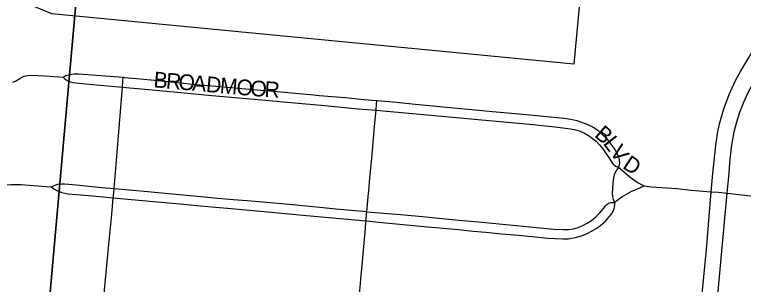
# Model space of a CAD drawing. Extents: x -209 to 4852, y 0 to 905.
# Drawn here: x 111.72 to 120.48, y 309.86 to 313.11 of the extents above; entities that cross this region are included whole.
import ezdxf

# ---------------------------------------------------------------- set-up
doc = ezdxf.new("R2010")
doc.units = 0
for name, color, linetype in [('GM_X_Airport_Location_Class_2', 7, 'Continuous'), ('GM_X_Airport_Location_Class_3', 7, 'Continuous'), ('GM_X_Minor_River', 7, 'Continuous'), ('GM_X_US_Location', 7, 'Continuous')]:
    doc.layers.add(name, color=color, linetype=linetype)

msp = doc.modelspace()

# ---------------------------------------------------------------- linework, layer by layer
at = {"layer": 'GM_X_Airport_Location_Class_2'}
for points in [[(120.0972, 310.975), (120.1155, 311.1929), (120.1467, 311.4975), (120.1715, 311.6747), (120.1963, 311.7933), (120.2473, 311.9704), (120.3118, 312.1446), (120.3881, 312.3128), (120.4482, 312.4205), (120.5455, 312.5798), (120.5778, 312.636), (120.6413, 312.7425), (120.7043, 312.8515), (120.7301, 312.9054), (120.7514, 312.9586)], [(120.2893, 310.9573), (120.3117, 311.2001), (120.3213, 311.3233), (120.3423, 311.51), (120.3745, 311.6939), (120.4049, 311.8144), (120.4428, 311.933), (120.4878, 312.051), (120.539, 312.1585), (120.5661, 312.2106), (120.5936, 312.2568), (120.6432, 312.3415), (120.7279, 312.487), (120.7857, 312.5857), (120.817, 312.6412), (120.8772, 312.7482), (120.9265, 312.8607), (120.9428, 312.9036)], [(111.7039, 312.2933), (111.7337, 312.3038), (111.7683, 312.3227), (111.7983, 312.3426), (111.8395, 312.3636), (111.8792, 312.3719), (111.9289, 312.3748), (112.0886, 312.3678), (112.3061, 312.3533)], [(112.3061, 312.3533), (112.3415, 312.3709), (112.3763, 312.3825), (112.4111, 312.3896), (112.4403, 312.3938), (112.4966, 312.3933), (113.0296, 312.3509)], [(112.3061, 312.3533), (112.3285, 312.3317), (112.3554, 312.3131), (112.394, 312.2961), (112.4257, 312.2869), (112.4588, 312.2826), (112.6643, 312.2645), (113.0198, 312.2319)], [(113.0198, 312.2319), (113.0257, 312.3028), (113.0296, 312.3509)], [(113.0296, 312.3509), (113.0404, 312.35), (113.1906, 312.3355), (113.4498, 312.3105), (113.9061, 312.2664), (114.1442, 312.245), (114.3642, 312.2252), (114.686, 312.1962), (114.8807, 312.1785), (115.0948, 312.1593), (115.2818, 312.1424), (115.3857, 312.1331), (115.6962, 312.1072), (115.927, 312.0858), (116.0789, 312.0718)], [(112.9192, 311.0137), (112.9471, 311.3504), (113.0198, 312.2319)], [(113.0198, 312.2319), (113.3346, 312.2032), (113.6381, 312.1754), (114.0949, 312.1338), (114.4208, 312.104), (114.6968, 312.0789), (115.0455, 312.0472), (115.4522, 312.0102), (115.8539, 311.9736), (116.0683, 311.9541)], [(116.0683, 311.9541), (116.0748, 312.0267), (116.0789, 312.0718)], [(116.0789, 312.0718), (116.1735, 312.0632), (116.3147, 312.0502), (116.5017, 312.0329), (116.9157, 311.9938), (117.2215, 311.9649), (117.4681, 311.9416), (117.6981, 311.9198), (117.9622, 311.8948), (118.1623, 311.8759), (118.3297, 311.8602), (118.4116, 311.8459), (118.4822, 311.8306), (118.5393, 311.8116), (118.6002, 311.7887), (118.6784, 311.7525), (118.7337, 311.7144), (118.7794, 311.6725), (118.8384, 311.6153), (118.8918, 311.5486), (118.9395, 311.4839), (118.9718, 311.4248), (118.9817, 311.3959), (118.9901, 311.3592), (118.9934, 311.3224), (118.9909, 311.2983), (118.9806, 311.2686)], [(115.9569, 310.7355), (115.9736, 310.9159), (115.9799, 310.9844), (115.9939, 311.1369), (116.0159, 311.379), (116.0327, 311.563), (116.0506, 311.7605), (116.0683, 311.9541)], [(116.0683, 311.9541), (116.2427, 311.9397), (116.5516, 311.9102), (117.9146, 311.7877), (118.2232, 311.7556), (118.407, 311.7333), (118.4659, 311.7213), (118.5223, 311.7037), (118.5755, 311.6802), (118.6216, 311.6529), (118.6668, 311.6203), (118.7132, 311.5823), (118.7547, 311.539), (118.793, 311.4918), (118.8281, 311.4425), (118.8652, 311.3848), (118.9013, 311.3257), (118.9203, 311.3061), (118.9396, 311.2915), (118.9579, 311.2789), (118.9806, 311.2686)], [(118.9806, 311.2686), (118.9658, 311.2459), (118.9453, 311.2162), (118.9294, 311.1795), (118.9212, 311.1402), (118.9149, 311.0837), (118.9089, 311.0151), (118.9067, 310.9561), (118.9103, 310.9151), (118.9185, 310.8836), (118.9375, 310.8474)], [(118.9806, 311.2686), (119.0572, 311.206), (119.1234, 311.1499), (119.2103, 311.0874), (119.292, 311.0445)], [(111.5366, 311.0347), (111.5893, 311.0509), (111.6317, 311.0596), (111.6811, 311.0636), (111.803, 311.0636), (112.1023, 311.0397), (112.1687, 311.0349)], [(112.1687, 311.0349), (112.1994, 311.0506), (112.245, 311.0646), (112.2865, 311.0695), (112.3221, 311.0695), (112.3756, 311.0668), (112.4656, 311.058), (112.7742, 311.028), (112.9192, 311.0137)], [(112.1687, 311.0349), (112.1964, 311.01), (112.232, 310.9902), (112.2581, 310.9771), (112.2902, 310.9653), (112.362, 310.9513), (112.469, 310.9416), (112.659, 310.9246), (112.8343, 310.909), (112.9095, 310.9021)], [(112.9095, 310.9021), (112.9114, 310.922), (112.9192, 311.0137)], [(112.9192, 311.0137), (113.2814, 310.9807), (113.6627, 310.9457), (113.9618, 310.9183), (114.1222, 310.9036), (114.3523, 310.8837), (114.5174, 310.8694), (114.7076, 310.8529), (115.0635, 310.8221), (115.2273, 310.8062), (115.3921, 310.7903), (115.5862, 310.7714), (115.7246, 310.758), (115.9487, 310.7362), (115.9569, 310.7355)], [(118.9375, 310.8474), (118.9623, 310.8703), (119.0214, 310.9122), (119.0772, 310.9451), (119.1365, 310.9762), (119.2039, 311.0071), (119.292, 311.0445)], [(119.292, 311.0445), (119.3758, 311.0361), (119.5016, 311.027), (119.6845, 311.0132), (119.8563, 310.996), (120.0972, 310.975)], [(119.9616, 309.4598), (120.0386, 310.2789), (120.0972, 310.975)], [(120.0378, 308.2708), (120.1731, 309.6916), (120.2893, 310.9573)], [(120.0972, 310.975), (120.1836, 310.9682)], [(120.1836, 310.9682), (120.2893, 310.9573)], [(120.2893, 310.9573), (120.43, 310.9414), (120.5317, 310.9306), (120.8394, 310.899), (120.8849, 310.8943), (120.8968, 310.8929)], [(112.7889, 309.6053), (112.8104, 309.8369), (112.8261, 310.0046), (112.8456, 310.2148), (112.8615, 310.3861), (112.8759, 310.5402), (112.8909, 310.7018), (112.9095, 310.9021)], [(112.9095, 310.9021), (113.4355, 310.8543), (113.7151, 310.8288), (113.9546, 310.8069), (114.1394, 310.7902), (114.2841, 310.777), (114.3698, 310.7692), (114.6778, 310.7411), (115.2324, 310.6906), (115.9482, 310.6245)], [(115.9482, 310.6245), (116.0986, 310.6106), (116.7304, 310.5509), (116.8318, 310.5414), (117.0561, 310.5201), (117.2369, 310.5031), (117.3878, 310.4888), (117.5747, 310.4711), (117.733, 310.4561), (117.9444, 310.4361), (118.1277, 310.4188), (118.3129, 310.4096), (118.3778, 310.4105), (118.4631, 310.4249), (118.5388, 310.4447), (118.6078, 310.4743), (118.6671, 310.5038), (118.7229, 310.5368), (118.769, 310.5729), (118.8249, 310.6223), (118.866, 310.6697), (118.8933, 310.7029), (118.9145, 310.7334), (118.9287, 310.7677), (118.9358, 310.7955), (118.9385, 310.821), (118.9375, 310.8474)], [(115.9569, 310.7355), (116.109, 310.7223), (116.2074, 310.7139), (116.3623, 310.7004), (116.6257, 310.6777), (116.9045, 310.6508), (117.0651, 310.6353), (117.2996, 310.6127), (117.5484, 310.5887), (117.9173, 310.5532), (118.2008, 310.5235), (118.322, 310.5196), (118.3827, 310.523), (118.4421, 310.5309), (118.4989, 310.5458), (118.554, 310.5688), (118.6074, 310.5973), (118.6584, 310.6291), (118.7097, 310.6748), (118.7558, 310.7176), (118.8051, 310.7775), (118.8242, 310.8042), (118.8416, 310.8232), (118.8633, 310.8358), (118.8905, 310.8445), (118.9189, 310.8472), (118.9375, 310.8474)], [(115.9482, 310.6245), (115.9552, 310.7162), (115.9569, 310.7355)], [(115.835, 309.3644), (115.8439, 309.4656), (115.8582, 309.6258), (115.8763, 309.827), (115.8902, 309.9714), (115.9012, 310.087), (115.9232, 310.3139), (115.9411, 310.5417), (115.9463, 310.5995), (115.9482, 310.6245)]]:
    msp.add_lwpolyline(points, dxfattribs=at)
at = {"layer": 'GM_X_Minor_River'}
for points in [[(112.672, 315.6227), (110.8632, 295.3198), (90.6477, 297.385), (92.468, 317.4452)], [(112.672, 315.6227), (132.7247, 313.81), (130.8333, 293.5535), (110.8632, 295.3198)]]:
    msp.add_lwpolyline(points, close=True, dxfattribs=at)
at = {"layer": 'GM_X_US_Location'}
msp.add_lwpolyline([(111.2446, 315.5623), (112.2583, 315.5089), (112.2698, 315.641), (112.7997, 315.3481), (113.0826, 315.3767), (113.5092, 315.341), (117.6868, 314.9243), (117.8328, 314.9237), (117.8722, 315.2599), (118.6935, 315.1799), (118.4457, 312.5097), (112.1702, 313.1121), (110.4242, 313.8394)], dxfattribs=at)

# ---------------------------------------------------------------- texts
at = {"layer": 'GM_X_Airport_Location_Class_3'}
for s, rotation, p in [('B', 354.94189, (113.3883, 312.2316)), ('R', 354.94786, (113.5377, 312.2184)), ('O', 354.94725, (113.6871, 312.2052)), ('A', 354.94725, (113.8531, 312.1905)), ('D', 354.94725, (114.0192, 312.1758)), ('M', 354.94679, (114.1852, 312.1611)), ('O', 354.94725, (114.3843, 312.1435)), ('O', 355.42061, (114.552, 312.1287)), ('R', 356.9386, (114.7236, 312.115)), ('B', 318.86662, (118.6831, 311.6464)), ('L', 307.67852, (118.7894, 311.5548)), ('V', 306.24914, (118.8701, 311.4502)), ('D', 326.50924, (119.0205, 311.2665))]:
    msp.add_text(s, height=0.1894, rotation=rotation, dxfattribs=at).set_placement(p)

doc.saveas('drawing.dxf')
